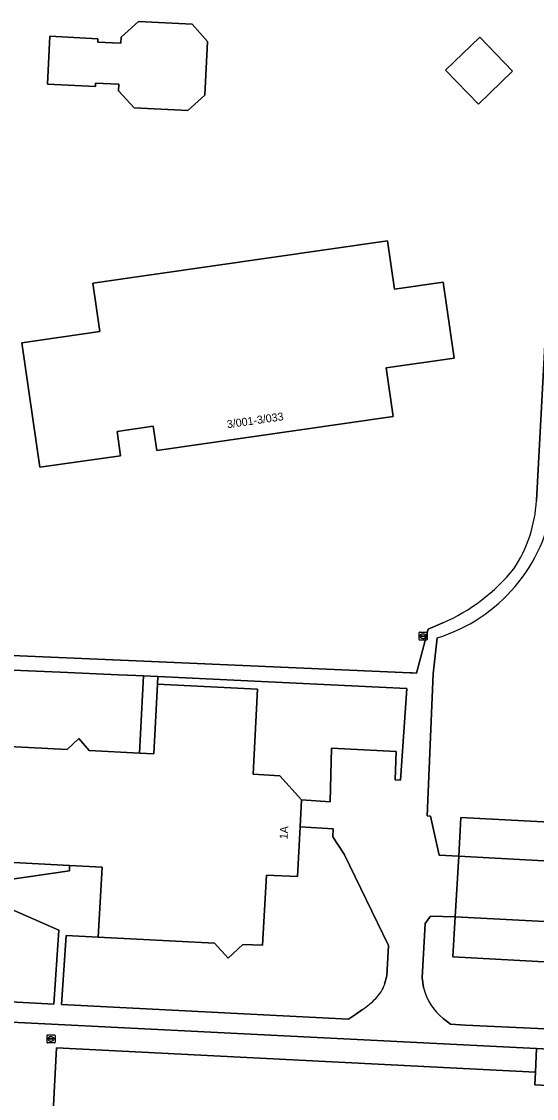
# Model space of a CAD drawing. Extents: x 161758 to 162722, y 384793 to 385405.
# Drawn here: x 161913.2 to 161977.6, y 385099.1 to 385233.7 of the extents above; entities that cross this region are included whole.
import ezdxf

# ---------------------------------------------------------------- set-up
doc = ezdxf.new("R2010")
doc.units = 0
for name, color, linetype in [('IMGEO_Brandkraan', 7, 'Continuous'), ('IMGEO_Erf', 7, 'Continuous'), ('IMGEO_Groenvoorziening', 7, 'Continuous'), ('IMGEO_Pand', 7, 'Continuous'), ('IMGEO_Pand_nummerreeks', 7, 'Continuous'), ('IMGEO_Parkeervlak_open', 7, 'Continuous'), ('IMGEO_Rijbaan_lokaal_open', 7, 'Continuous'), ('IMGEO_Rioolput', 7, 'Continuous'), ('IMGEO_Voetpad_open', 7, 'Continuous')]:
    doc.layers.add(name, color=color, linetype=linetype)

msp = doc.modelspace()

# ---------------------------------------------------------------- linework, layer by layer
at = {"layer": 'IMGEO_Brandkraan'}
for p, q in [((161962.91, 385156.44), (161962.91, 385157.29)), ((161962.99, 385157.36), (161963.84, 385157.36)), ((161963.17, 385156.86), (161963.17, 385156.87)), ((161963.21, 385156.91), (161963.61, 385156.91)), ((161963.61, 385156.82), (161963.21, 385156.82)), ((161963.4, 385157.14), (161963.42, 385157.14)), ((161963.65, 385156.87), (161963.65, 385156.86)), ((161963.91, 385157.29), (161963.91, 385156.44)), ((161963.84, 385156.36), (161962.99, 385156.36)), ((161963.42, 385156.58), (161963.4, 385156.58))]:
    msp.add_line(p, q, dxfattribs=at)
for points in [[(161962.91, 385156.44), (161962.91, 385157.29)], [(161962.99, 385157.36), (161963.84, 385157.36)], [(161963.91, 385157.29), (161963.91, 385156.44)], [(161963.84, 385156.36), (161962.99, 385156.36)]]:
    msp.add_lwpolyline(points, dxfattribs=at)
for centre, radius, start, end in [((161962.99, 385157.29), 0.0765, 91.552, 178.448), ((161962.99, 385157.29), 0.0765, 91.552, 178.448), ((161963.21, 385156.87), 0.0403, 85.8775, 175.7526), ((161963.21, 385156.86), 0.0366, 178.938, 274.7102), ((161963.62, 385156.87), 0.0386, 1.7309, 96.639), ((161963.61, 385156.86), 0.043, 264.8664, 352.4533), ((161963.84, 385157.29), 0.0765, 1.552, 88.448), ((161963.84, 385157.29), 0.0765, 1.552, 88.448), ((161962.99, 385156.44), 0.0765, 181.552, 268.448), ((161962.99, 385156.44), 0.0765, 181.552, 268.448), ((161963.84, 385156.44), 0.0765, 271.552, 358.448), ((161963.84, 385156.44), 0.0765, 271.552, 358.448)]:
    msp.add_arc(centre, radius, start, end, dxfattribs=at)
for centre, major_axis, ratio, start_param, end_param in [((161963.4, 385156.86), (-0.387, 0.002), 0.722429, 4.712389, 7.853982), ((161963.42, 385156.86), (-0.39, 0.002), 0.717154, 1.570796, 4.712389)]:
    msp.add_ellipse(centre, major_axis=major_axis, ratio=ratio, start_param=start_param, end_param=end_param, dxfattribs=at)
at = {"layer": 'IMGEO_Erf'}
for points in [[(161934.02, 385222.54), (161927.31, 385222.87), (161925.37, 385225.01), (161925.39, 385225.82), (161924.38, 385225.87), (161922.49, 385225.96), (161922.48, 385225.52), (161916.47, 385225.81), (161916.76, 385231.82), (161922.77, 385231.51), (161922.75, 385231.07), (161924.61, 385230.98), (161925.65, 385230.94), (161925.68, 385231.71), (161927.84, 385233.65), (161934.55, 385233.31), (161936.49, 385231.17), (161936.16, 385224.47)], [(161966.23, 385227.58), (161970.51, 385231.7), (161974.61, 385227.44), (161970.33, 385223.32)], [(161958.98, 385206.27), (161959.86, 385200.2), (161965.93, 385201.07), (161967.3, 385191.59), (161958.8, 385190.38), (161959.67, 385184.29), (161930.13, 385180.05), (161929.69, 385183.09), (161925.18, 385182.43), (161925.61, 385179.4), (161915.53, 385177.96), (161913.28, 385193.51), (161923.04, 385194.91), (161922.16, 385200.98)]]:
    msp.add_lwpolyline(points, close=True, dxfattribs=at)
for points in [[(161977.59, 385173.79), (161979.29, 385205.66)], [(161965.16, 385156.64), (161964.69, 385152.15), (161963.95, 385134.41), (161964.36, 385134.39), (161965.45, 385129.52), (161967.88, 385129.39), (161968.14, 385134.19), (161989.57, 385133.1), (162003.08, 385132.41), (162003.36, 385132.4), (162003.49, 385135.03), (161985.28, 385135.93), (161985.55, 385142.31), (162009.42, 385141.2), (162009.57, 385144.22), (162026.66, 385143.46), (162027.23, 385153.37), (162027.32, 385155.33), (162027.69, 385162.43)], [(161901.23, 385154.93), (161902.89, 385157.22), (161908.26, 385155.48), (161908.37, 385158.54), (161910.26, 385158.5), (161910.05, 385154.51), (161927.58, 385153.78), (161958.97, 385152.4), (161961.82, 385152.28), (161962.06, 385152.27), (161962.61, 385152.24), (161964.07, 385157.72), (161965.89, 385158.53)], [(161917.59, 385105.41), (161977.45, 385102.4), (161977.6, 385105.33), (161906.14, 385108.94)], [(161902.28, 385069.94), (161923.17, 385068.89), (161923.58, 385077.12), (161935.54, 385076.52), (161936.08, 385086.96), (161926.28, 385087.45), (161926.44, 385090.58), (161926.17, 385090.6), (161925.8, 385083.13), (161916.49, 385083.6), (161916.54, 385084.5), (161916.8, 385089.51), (161916.87, 385091), (161917.59, 385105.41)]]:
    msp.add_lwpolyline(points, dxfattribs=at)
for centre, radius, start, end in [((161959.03, 385176.58), 20.86, 287.1133, 352.1695), ((161960.36, 385174.77), 17.26, 326.5777, 356.746), ((161956.25, 385180.46), 23.96, 293.7191, 320.6111)]:
    msp.add_arc(centre, radius, start, end, dxfattribs=at)
at = {"layer": 'IMGEO_Groenvoorziening'}
for points in [[(161928.47, 385151.91), (161927.52, 385151.95), (161925.36, 385152.04), (161918.08, 385152.35), (161908.14, 385152.77)], [(161894.35, 385127.12), (161911.18, 385126.36), (161919.21, 385127.53), (161919.24, 385128.21), (161902.88, 385129.08), (161903.05, 385132.18), (161896.04, 385132.58), (161896.4, 385139.57), (161896.63, 385143.83), (161903.61, 385143.48), (161918.94, 385142.7), (161920.38, 385144.06), (161921.68, 385142.57), (161927.98, 385142.25), (161928.47, 385151.91)], [(161958.61, 385113.39), (161958.88, 385114.43), (161959.09, 385118.2), (161953.56, 385129.64), (161952.14, 385131.77), (161952.17, 385132.81), (161948.06, 385133.03), (161947.74, 385126.85), (161943.83, 385126.99), (161943.34, 385118.24), (161940.9, 385118.33), (161939.07, 385116.65), (161937.35, 385118.51)], [(161917.9, 385120.15), (161910.96, 385123.18), (161910.1, 385123.22), (161909.41, 385122.1), (161908.57, 385121.13), (161906.84, 385120.57), (161890.67, 385121.4)], [(161996.73, 385115.18), (161996.68, 385115.18), (161994.55, 385115.29), (161967.14, 385116.81), (161967.41, 385121.79), (161964.34, 385121.88), (161963.7, 385120.97), (161963.32, 385114.17), (161963.48, 385112.97)], [(161905.69, 385111.49), (161917.25, 385110.9), (161917.9, 385120.15)], [(161937.35, 385118.51), (161922.82, 385119.26), (161918.83, 385119.45), (161918.22, 385110.85), (161923.88, 385110.56), (161954.1, 385109.02), (161954.99, 385109.61), (161955.86, 385110.23)], [(161965.95, 385109.1), (161966.86, 385108.37), (161968.71, 385108.28), (161977.77, 385107.84), (161990.05, 385107.16), (161993.83, 385106.99), (161993.93, 385108.7), (161999.59, 385108.36)]]:
    msp.add_lwpolyline(points, dxfattribs=at)
msp.add_lwpolyline([(161961.39, 385150.32), (161930.25, 385151.82), (161930.21, 385150.85), (161942.73, 385150.22), (161942.2, 385139.61), (161945.51, 385139.43), (161948.23, 385136.42), (161951.8, 385136.16), (161951.97, 385142.86), (161960.05, 385142.45), (161959.91, 385138.9), (161960.61, 385138.85)], close=True, dxfattribs=at)
for centre, radius, start, end in [((161954.16, 385114.9), 4.71, 315.3958, 341.2395), ((161970, 385114.41), 6.68, 192.4566, 232.6372), ((161949.2, 385119.92), 11.76, 304.4887, 314.9652)]:
    msp.add_arc(centre, radius, start, end, dxfattribs=at)
at = {"layer": 'IMGEO_Pand'}
for points in [[(161924.38, 385225.87), (161925.39, 385225.82), (161925.37, 385225.01), (161927.31, 385222.87), (161934.02, 385222.54), (161936.16, 385224.47), (161936.49, 385231.17), (161934.55, 385233.31), (161927.84, 385233.65), (161925.68, 385231.71), (161925.65, 385230.94), (161924.61, 385230.98), (161922.75, 385231.07), (161922.77, 385231.51), (161916.76, 385231.82), (161916.47, 385225.81), (161922.48, 385225.52), (161922.49, 385225.96)], [(161970.51, 385231.7), (161966.23, 385227.58), (161970.33, 385223.32), (161974.61, 385227.44)], [(161965.93, 385201.07), (161959.86, 385200.2), (161958.98, 385206.27), (161922.16, 385200.98), (161923.04, 385194.91), (161913.28, 385193.51), (161915.53, 385177.96), (161925.61, 385179.4), (161925.18, 385182.43), (161929.69, 385183.09), (161930.13, 385180.05), (161959.67, 385184.29), (161958.8, 385190.38), (161967.3, 385191.59)]]:
    msp.add_lwpolyline(points, close=True, dxfattribs=at)
for points in [[(161902.88, 385129.08), (161919.24, 385128.21), (161923.31, 385127.99), (161922.82, 385119.26), (161937.35, 385118.51), (161939.07, 385116.65), (161940.9, 385118.33), (161943.34, 385118.24), (161943.83, 385126.99), (161947.74, 385126.85), (161948.06, 385133.03), (161948.23, 385136.42), (161945.51, 385139.43), (161942.2, 385139.61), (161942.73, 385150.22), (161930.21, 385150.85), (161929.77, 385142.16), (161927.98, 385142.25), (161921.68, 385142.57), (161920.38, 385144.06), (161918.94, 385142.7), (161903.61, 385143.48)], [(161985.24, 385093.71), (161979.77, 385100.88), (161979.76, 385100.69), (161977.38, 385100.81), (161977.45, 385102.4), (161917.59, 385105.41), (161916.87, 385091)]]:
    msp.add_lwpolyline(points, dxfattribs=at)
at = {"layer": 'IMGEO_Parkeervlak_open'}
for points in [[(162003.08, 385132.41), (161989.57, 385133.1), (161968.14, 385134.19), (161967.88, 385129.39), (162002.8, 385127.45), (162002.97, 385130.51)], [(162002.49, 385119.97), (161967.41, 385121.79), (161967.14, 385116.81), (161994.55, 385115.29), (161996.68, 385115.18), (161996.73, 385115.18), (162002.3, 385115.02)]]:
    msp.add_lwpolyline(points, close=True, dxfattribs=at)
at = {"layer": 'IMGEO_Rijbaan_lokaal_open'}
msp.add_lwpolyline([(162002.72, 385126.05), (162002.8, 385127.45), (161967.88, 385129.39), (161967.41, 385121.79), (162002.49, 385119.97)], close=True, dxfattribs=at)
at = {"layer": 'IMGEO_Rioolput'}
for p, q in [((161916.42, 385106.12), (161916.42, 385106.97)), ((161916.49, 385107.04), (161917.34, 385107.04)), ((161917.42, 385106.97), (161917.42, 385106.12)), ((161917.34, 385106.04), (161916.49, 385106.04)), ((161916.67, 385106.54), (161916.67, 385106.55)), ((161917.11, 385106.5), (161916.71, 385106.5)), ((161916.72, 385106.59), (161917.11, 385106.59)), ((161916.9, 385106.82), (161916.93, 385106.82)), ((161916.93, 385106.26), (161916.9, 385106.26)), ((161917.16, 385106.55), (161917.16, 385106.54))]:
    msp.add_line(p, q, dxfattribs=at)
for points in [[(161916.42, 385106.12), (161916.42, 385106.97)], [(161916.49, 385107.04), (161917.34, 385107.04)], [(161917.42, 385106.97), (161917.42, 385106.12)], [(161917.34, 385106.04), (161916.49, 385106.04)]]:
    msp.add_lwpolyline(points, dxfattribs=at)
for centre, radius, start, end in [((161916.49, 385106.97), 0.0765, 91.552, 178.448), ((161916.49, 385106.97), 0.0765, 91.552, 178.448), ((161917.34, 385106.97), 0.0765, 1.552, 88.448), ((161917.34, 385106.97), 0.0765, 1.552, 88.448), ((161916.49, 385106.12), 0.0765, 181.552, 268.448), ((161916.49, 385106.12), 0.0765, 181.552, 268.448), ((161916.71, 385106.55), 0.0403, 85.8775, 175.7526), ((161916.71, 385106.54), 0.0366, 178.938, 274.7102), ((161917.12, 385106.55), 0.0386, 1.7309, 96.639), ((161917.12, 385106.54), 0.043, 264.8664, 352.4533), ((161917.34, 385106.12), 0.0765, 271.552, 358.448), ((161917.34, 385106.12), 0.0765, 271.552, 358.448)]:
    msp.add_arc(centre, radius, start, end, dxfattribs=at)
for centre, major_axis, ratio, start_param, end_param in [((161916.9, 385106.54), (-0.387, 0.002), 0.722429, 4.712389, 7.853982), ((161916.93, 385106.54), (-0.39, 0.002), 0.717154, 1.570796, 4.712389)]:
    msp.add_ellipse(centre, major_axis=major_axis, ratio=ratio, start_param=start_param, end_param=end_param, dxfattribs=at)
at = {"layer": 'IMGEO_Voetpad_open'}
for points in [[(161979.29, 385205.66), (161977.59, 385173.79)], [(161965.89, 385158.53), (161964.07, 385157.72), (161962.61, 385152.24), (161962.06, 385152.27), (161961.82, 385152.28), (161958.97, 385152.4), (161927.58, 385153.78), (161910.05, 385154.51), (161910.26, 385158.5), (161908.37, 385158.54), (161908.26, 385155.48), (161902.89, 385157.22), (161901.23, 385154.93)], [(161963.48, 385112.97), (161963.32, 385114.17), (161963.7, 385120.97), (161964.34, 385121.88), (161967.41, 385121.79), (161967.88, 385129.39), (161965.45, 385129.52), (161964.36, 385134.39), (161963.95, 385134.41), (161964.69, 385152.15), (161965.16, 385156.64)], [(161908.14, 385152.77), (161918.08, 385152.35), (161925.36, 385152.04), (161927.52, 385151.95), (161928.47, 385151.91), (161930.25, 385151.82), (161961.39, 385150.32), (161960.61, 385138.85), (161959.91, 385138.9), (161960.05, 385142.45), (161951.97, 385142.86), (161951.8, 385136.16), (161948.23, 385136.42), (161948.06, 385133.03), (161952.17, 385132.81), (161952.14, 385131.77), (161953.56, 385129.64), (161959.09, 385118.2), (161958.88, 385114.43), (161958.61, 385113.39)], [(161955.86, 385110.23), (161954.99, 385109.61), (161954.1, 385109.02), (161923.88, 385110.56), (161918.22, 385110.85), (161918.83, 385119.45), (161922.82, 385119.26), (161923.31, 385127.99), (161919.24, 385128.21), (161919.21, 385127.53), (161911.18, 385126.36), (161894.35, 385127.12)], [(161894.92, 385123.95), (161910.1, 385123.22), (161910.96, 385123.18), (161917.9, 385120.15), (161917.25, 385110.9), (161905.69, 385111.49)], [(161906.14, 385108.94), (161977.6, 385105.33), (161995.88, 385104.4), (162000.83, 385104.15), (162000.14, 385090.22)], [(161998.61, 385106.78), (161993.83, 385106.99), (161990.05, 385107.16), (161977.77, 385107.84), (161968.71, 385108.28), (161966.86, 385108.37), (161965.95, 385109.1)], [(162000.14, 385090.22), (162000.83, 385104.15), (161995.88, 385104.4), (161977.6, 385105.33), (161977.45, 385102.4), (161977.38, 385100.81), (161979.76, 385100.69), (161979.77, 385100.88), (161985.24, 385093.71), (161985.82, 385092.94), (161990.12, 385096.3), (161990.03, 385094.35), (161989.72, 385094.12), (161989.89, 385093.9)]]:
    msp.add_lwpolyline(points, dxfattribs=at)
msp.add_lwpolyline([(161930.21, 385150.85), (161930.25, 385151.82), (161928.47, 385151.91), (161927.98, 385142.25), (161929.77, 385142.16)], close=True, dxfattribs=at)
for centre, radius, start, end in [((161959.03, 385176.58), 20.86, 287.1133, 352.1695), ((161960.36, 385174.77), 17.26, 326.5777, 356.746), ((161956.25, 385180.46), 23.96, 293.7191, 320.6111), ((161954.16, 385114.9), 4.71, 315.3958, 341.2395), ((161970, 385114.41), 6.68, 192.4566, 232.6372), ((161949.2, 385119.92), 11.76, 304.4887, 314.9652)]:
    msp.add_arc(centre, radius, start, end, dxfattribs=at)

# ---------------------------------------------------------------- texts
at = {"layer": 'IMGEO_Pand_nummerreeks'}
for s, rotation, p in [('3/001-3/033', 8.1818, (161938.97, 385182.83)), ('1A', 87.0495, (161946.48, 385131.47))]:
    msp.add_text(s, height=1, rotation=rotation, dxfattribs=at).set_placement(p)

doc.saveas('drawing.dxf')
